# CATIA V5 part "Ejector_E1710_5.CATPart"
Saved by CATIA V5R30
Part number: Vyhazovac_2.5x160_3
Nomenclature: E1710/2.5x160
Description: MEUSBURGER
Property "Material": "1.221"
Publications: "__DrillHole", "Base"
Bounding box of the stored display mesh (mm): x -2.499 to 2.499, y -2.499 to 2.499, z 0 to 154.3
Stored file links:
  E:\Bakalarka\Model\Forma_v7\Ejector_E1710_5.CATPart
  E:\dev\MoldDesign\intel_a\startup\components\MoldCatalog\Ejector\Meusburger\Ejector_E1710\TableE1710.txt
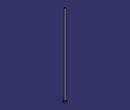
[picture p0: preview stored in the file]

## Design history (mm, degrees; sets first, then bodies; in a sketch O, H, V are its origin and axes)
Parameters
  Ref = "E1710/2.5x160" {design table}
  D1 = 2.5 mm {design table}
  D3 = 5 mm {design table}
  L = 160 mm {design table}
  L3 = 2 mm {design table}
  R = 0.3 mm {design table}
  k_d3 = 6 mm {design table}
  k_d1 = 2.7 mm {design table}
  k_F = 0.3 mm {design table}
  kl = 17 mm {design table}
  Mat = "1.221" {design table}
  HeatTreat = "ISO6751" {design table}
  Offset_Parting = 10 mm
  Anti_Rotation = "Normal"
  Anti_Rotation_D = 1.55 mm
  Anti_Rotation_D_Icut = 1.55 mm
  Add_Length_L = 0.0877 mm
  Add_Length_D3 = 0 mm
  SupplierRef = "Meusburger 2017"
  BmpRef = "F_MldEjectorD1"
  DrillHole_Length = 225 mm
  ValidationTest = false
  Anti_Rotation_D_min = 1.55 mm {= OffSet_D1 /2}
  Anti_Rotation_D_max = 2.425 mm {= D3/2-0.075mm}
  Anti_Rotation_D_ref = 1.55 mm {= Anti_Rotation_D}
  Anti_Rotation_D_Icut_ref = 1.55 mm {= Anti_Rotation_D_Icut}
  Anti_Rotation_Ref_Icut = 2.3246 mm
  Offset_L = 20 mm
  D = 2.5 mm {= D1}
  OffSet_D1 = 3.1 mm {= D1+2*R}
  OffSet_D3 = 6 mm {= D3+1mm}
  XG_Split = -120 mm
  YG_Split = -57.5 mm
  ZG_Split = -198 mm
  DirX_Split = 0 mm
  DirY_Split = 0 mm
  DirZ_Split = 1 mm
Set1 "BaseBody"
  Point1 "Base": (0, 0, 0)
  Plane1: type Offset, RefPlane xy-plane, Offset 225 {= DrillHole_Length}, reversed
  Sketch1 "Sketch.2" on xy-plane, origin (0, 0, 0), H (1, 0, 0), V (0, 1, 0)
    point P1 (-0.46, 1.1623)
    point P2 (0.46, 1.1623)
    construction line L1 (-0.46, 1.1623) -> (0.46, 1.1623)
    point P3 (0.46, -1.1623)
    line L2 (0.46, -1.1623) -> (0.46, 1.1623)
    point P4 (-0.46, -1.1623)
    construction line L3 (0.46, -1.1623) -> (-0.46, -1.1623)
    line L4 (-0.46, 1.1623) -> (-0.46, -1.1623)
    point P5 (-0.21, 1.1623)
    arc A1 centre (-0.21, 1.1623) radius 0.25 from (-0.21, 1.4123) to (-0.46, 1.1623) ccw
    point P7 (0.21, 1.1623)
    point P8 (0.21, 1.4123)
    arc A2 centre (0.21, 1.1623) radius 0.25 from (0.46, 1.1623) to (0.21, 1.4123) ccw
    line L5 (-0.21, 1.4123) -> (0.21, 1.4123)
    point P9 (-0.46, -1.1623)
    arc A3 centre (-0.21, -1.1623) radius 0.25 from (-0.46, -1.1623) to (-0.21, -1.4123) ccw
    point P11 (0.21, -1.4123)
    line L6 (-0.21, -1.4123) -> (0.21, -1.4123)
    point P12 (0.46, -1.1623)
    arc A4 centre (0.21, -1.1623) radius 0.25 from (0.21, -1.4123) to (0.46, -1.1623) ccw
    point P14 (-0.46, 1.1623)
    point P15 (-0.46, -1.1623)
    point P16 (0.46, 1.1623)
    point P17 (0.46, -1.1623)
    reference projected circle E1 centre (0, 0) radius 1.25 from edge [face of Shaft1 from Sketch2.L3 | face of Shaft1 from Sketch2.L4]
    reference projected circle E2 centre (0, 0) radius 1.25 from edge [face of Shaft1 from Sketch2.L3 | face of Shaft1 from Sketch2.L4]
    reference projected circle E3 centre (0, 0) radius 1.25 from edge [face of Shaft1 from Sketch2.L3 | face of Shaft1 from Sketch2.L4]
    reference projected circle E4 centre (0, 0) radius 1.25 from edge [face of Shaft1 from Sketch2.L3 | face of Shaft1 from Sketch2.L4]
    point P18 (-0.46, -1.1623)
    point P19 (-0.21, -1.4123)
    point P20 (0.21, -1.4123)
    point P21 (0.46, -1.1623)
    point P22 (-0.21, -1.4123)
    point P23 (0.21, -1.4123)
    distance P14 P15 = 2.3246 (reference)
    distance P16 P17 = 2.3246 (reference)
    distance L1 P14 = 0 (reference)
    radius A1 = 1.25
    distance L4 V = 1.56
    distance L2 V = 2.435
    distance L5 L6 = 5
    horizontal: L1 H, L3 H, L5 H
    vertical: L2 V, L4 V
    coincidence: P5 L1, P7 L1, P3 P12, P14 L4, P15 L4, P16 L2, P17 L2, P14 E1, P15 E2, P16 E3, P17 E4, P3 P21, P4 P18, P20 P23, P19 P22
    tangency: A1 L4, A2 L2, A2 L5, A1 L5
    symmetry: P1 P9 H, A1 A3 H, P8 P11 H, L5 L6 H, P2 P12 H, A2 A4 H
  DatumSurface1
Body1 "PartBody" (main body)
  Sketch2 "Sketch.1" on zx-plane, origin (0, 0, 0), H (-1, 0, 0), V (0, 0, 1)
    point P1 (0, 160)
    line L1 (1.25, 160) -> (0, 160)
    line L2 (1.25, 2) -> (1.25, 160)
    line L3 (2.5, 2) -> (1.25, 2)
    line L4 (2.5, 0) -> (2.5, 2)
    point P5 (0, 0)
    line L5 (0, 0) -> (2.5, 0)
    point P6 (0, 160)
    axis line L6 (0, 160) -> (0, 0)
    point P7 (0, 0)
    point P8 (1.25, 2)
    point P9 (1.25, 2)
    line L7 (0, 160) -> (0, 0)
    distance L5 L3 = 2 {= L3}
    distance L5 L1 = 160 {= L}
    distance L2 L6 = 1.25 {= D1 /2}
    distance L4 L6 = 2.5 {= D3 /2}
    coincidence: L6 P5, P1 L6, L5 H, L6 V, P7 O, P6 P1, P8 P9
    vertical: L2 V, L7 V
    horizontal: L1 H
  Shaft1 "Shaft.1": profile Sketch2, axis Sketch2.L6, angle 360
  Pocket1 "Pocket.1": profile Sketch1, direction (0, 0, 1), length 3, outer side, deactivated
  Pocket2 "Pocket.2": profile Sketch1, direction (0, 0, 1), length 3, outer side, deactivated
  Fillet1: radius 0.3 {= R}, on edge [face of Shaft1 from Sketch2.L2 | face of Shaft1 from Sketch2.L3]
  Pocket3: profile face of Shaft1 from Sketch2.L1, direction along face of Shaft1 from Sketch2.L1 reversed, up to face of DatumSurface1
Body2 "__DrillHole"
  Sketch3 "Sketch.3" on face of Shaft1, origin (0, 0, 0), H (1, 0, 0), V (0, -1, 0)
    point P1 (0, 0)
    reference projected point E1 (0, 0) from Point1
    coincidence: E1 P1
  Hole1 "Hole.1": placed by Sketch3, at (0, 0, 0) direction (0, 0, 1), diameter 3.1 {= OffSet_D1}, depth 140 {= L-Offset_L}
  Sketch4 "Sketch.4" on face of Shaft1, origin (0, 0, 0), H (1, 0, 0), V (0, -1, 0)
    point P1 (0, 0)
    reference projected point E1 (0, 0) from Point1
    coincidence: E1 P1
  Hole2 "Hole.2": placed by Sketch4, at (0, 0, 0) direction (0, 0, 1), diameter 2.5 {= D1}, depth 160 {= L}
  Sketch5 "Sketch.5" on face of Shaft1 from Sketch2.L3, origin (0, 0, 2), H (1, 0, 0), V (0, 1, 0)
    point P1 (0, 0)
    reference projected point E1 (0, 0) from Point1
    coincidence: E1 P1
  Hole3 "Hole.3": placed by Sketch5, at (0, 0, 2) direction (0, 0, -1), diameter 6 {= OffSet_D3}, depth 227 {= L3 +DrillHole_Length}
  Chamfer1: length 0.3 {= k_F}, angle 45, on edge [face of Hole1 | face of Hole3]
  Body3 "__Body.1"
    Pocket4 "Pocket.3": profile Sketch1, direction (0, 0, -1), length 225, opposite side length 2, deactivated
  Assemble1: tool Body3
  Chamfer2: length 0.3 {= k_F}, angle 45, on edge [start face of Pocket4 | face of Hole1], deactivated
  Body4 "__Body.2"
    Pocket5 "Pocket.4": profile Sketch1, direction (0, 0, -1), length 225, opposite side length 2, deactivated
  Assemble2: tool Body4
  Chamfer3: length 0.3 {= k_F}, angle 45, on edge [start face of Pocket5 | face of Hole1], deactivated
Relations
  design table "TableE1710", configuration 134, drives Ref, D1, D3, L, L3, R, k_d3, k_d1, k_F, kl, Mat, HeatTreat
  Offset_L = 20mm (deactivated)
  rule "Cut_Head_rule":
    let sketch_cut (length)
    let PartBody_Pocket_Sketch (Boolean)
    let I_PartBody_Pocket (Boolean)
    let D_PartBody_Pocket (Boolean)
    let N_DrillHole_Hole (Boolean)
    let N_DrillHole_Hole_Sketch (Boolean)
    let I_DrillHole_Pocket (Boolean)
    let D_DrillHole_Pocket (Boolean)
    /* --------------------------------------------------------------------------------------*/
    if Anti_Rotation =="Normal"
    {
    	sketch_cut=Anti_Rotation_D_max
    	PartBody_Pocket_Sketch = false
    	I_PartBody_Pocket = false
    	D_PartBody_Pocket = false
    	N_DrillHole_Hole = true
    	N_DrillHole_Hole_Sketch = true
    	I_DrillHole_Pocket = false
    	D_DrillHole_Pocket = false
    	Chamfer1.Activity= true
    	Chamfer2.Activity= false
    	Chamfer3.Activity= false
    }
    if Anti_Rotation == "I_Cut"
    {
    	sketch_cut=Anti_Rotation_D_Icut_ref
    	PartBody_Pocket_Sketch = true
    	I_PartBody_Pocket = true
    	D_PartBody_Pocket = false
    	N_DrillHole_Hole = false
    	N_DrillHole_Hole_Sketch = false
    	I_DrillHole_Pocket = true
    	D_DrillHole_Pocket = false
    	Chamfer1.Activity= false
    	Chamfer2.Activity= true
    	Chamfer3.Activity= false
    }
    if Anti_Rotation =="D_Cut"
    {
    	sketch_cut=Anti_Rotation_D_max
    	PartBody_Pocket_Sketch = true
    	I_PartBody_Pocket = false
    	D_PartBody_Pocket = true
    	N_DrillHole_Hole = false
    	N_DrillHole_Hole_Sketch = false
    	I_DrillHole_Pocket = false
    	D_DrillHole_Pocket = true
    	Chamfer1.Activity= false
    	Chamfer2.Activity= false
    	Chamfer3.Activity= true
    }
    /* --------------------------------------------------------------------------------------*/
    Sketch1.distance(L2 V) = sketch_cut+0.01mm
    Sketch1.distance(L4 V) =Anti_Rotation_D_ref+0.01mm
    Sketch1.radius(A1) =D/2
    Pocket4.FirstLimit.Depth = DrillHole_Length
    Pocket5.FirstLimit.Depth = DrillHole_Length
    Pocket1.FirstLimit.Depth = L3+1mm
    Pocket2.FirstLimit.Depth = L3+1mm
    Pocket4.SecondLimit.Depth = L3
    Pocket5.SecondLimit.Depth =L3
    Pocket1.Activity = I_PartBody_Pocket
    Pocket2.Activity = D_PartBody_Pocket
    Sketch1.Activity =PartBody_Pocket_Sketch
    Hole3.Activity= N_DrillHole_Hole
    Sketch5.Activity = N_DrillHole_Hole_Sketch
    Pocket4.Activity = I_DrillHole_Pocket
    Pocket5.Activity  = D_DrillHole_Pocket
  rule "Anti_Rotation_Icut_constrain":
    let Ref1(length)
    let Ref2(length)
    let Ref3(length)
    let Diam1(length)
    let Diam2(length)
    let Add_Length_Lmin (length)
    Ref1=Sketch1.distance(P14 P15)
    Ref2=Sketch1.distance(P16 P17)
    Diam1=D
    Diam2=D3
    /* --------------------------------------------------------------------*/
    if Ref1 >Ref2
    	Anti_Rotation_Ref_Icut = Ref1
    else
    	Anti_Rotation_Ref_Icut  =Ref2
    Add_Length_D3 .InferiorRange=Anti_Rotation_Ref_Icut /2+Diam1/2 -Diam2/2
    if Add_Length_D3 .InferiorRange<0mm
    	Add_Length_D3 .InferiorRange=0mm
    if ValidationTest == "true"
    	Ref3   = 2*Add_Length_L +Anti_Rotation_Ref_Icut  +2*Diam1/2
    else
    	Ref3  =Diam2+2*Add_Length_D3
    if Ref3 <Diam2
    {
    	Ref3 =Diam2
    }
    /* --------------------------------------------------------------------*/
    Sketch1.distance(L5 L6) = Ref3
    Add_Length_L .InferiorRange=Diam2/2-Anti_Rotation_Ref_Icut/2-Diam1/2
    Add_Length_Lmin=Diam2/2-Anti_Rotation_Ref_Icut/2-Diam1/2
    if Add_Length_Lmin<0mm
    	Add_Length_L .InferiorRange=0mm
    else
    	Add_Length_L .InferiorRange=Add_Length_Lmin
